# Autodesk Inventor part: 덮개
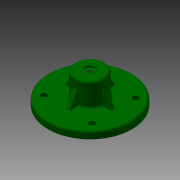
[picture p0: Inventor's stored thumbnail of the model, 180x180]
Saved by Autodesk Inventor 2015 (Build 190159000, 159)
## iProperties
Created: 2017-08
Part Number: 덮개
Material: 알루미늄 6061
Document SubType Name: Modeling
Designer: mduedu
Density: 2.71 g/cm^3
Mass: 358.12 g
Surface Area: 294.002 cm^2
Volume: 132.148 cm^3
Appearance: 알루미늄 - 평지
Author: mduedu
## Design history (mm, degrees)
sketch "스케치1"
  geometry: C1 r 57.5 at (0, 0); 1 further point
  constraints: 1 centre point, 1 coincident
  dimensions: "d69" = 115 diameter of C1
extrude "돌출1" new body sketch "스케치1" distance "d5" = 10; taper "d6" = 0 deg
sketch "스케치2"
  geometry: C1 r 20 at (0, 0); 1 further point
  constraints: 1 centre point, 1 coincident
  dimensions: "d55" = 40 diameter of C1
extrude "돌출2" join sketch "스케치2" distance "d9" = 32; taper "d10" = 0 deg
sketch "스케치3"
  geometry: L1 (-26, -26)-(26, -26); L2 (26, -26)-(26, 26); L3 (26, 26)-(-26, 26); L4 (-26, 26)-(-26, -26); L5 (-26, -26)-(26, 26); L6 (26, -26)-(-26, 26); 1 further point
  constraints: 12 end point, 2 midpoint, 2 parallel, 2 perpendicular, 1 horizontal
  dimensions: "d11" = 52 distance of L3.end L2.end
extrude "돌출3" join sketch "스케치3" distance "d12" = 6; taper "d13" = 0 deg
sketch "스케치4"
  geometry: L1 (-17, -17)-(17, -17); L2 (17, -17)-(17, 17); L3 (17, 17)-(-17, 17); L4 (-17, 17)-(-17, -17); L5 (-17, -17)-(17, 17); L6 (17, -17)-(-17, 17); 1 further point
  constraints: 12 end point, 2 midpoint, 2 parallel, 2 perpendicular, 1 horizontal
  dimensions: "d14" = 34 distance of L2.end L3.end
extrude "돌출4" cut sketch "스케치4" distance "d16" = 5; taper "d17" = 0 deg
sketch "스케치5"
  geometry: C1 r 9 at (0, 0); 1 further point
  constraints: 1 centre point, 1 coincident
  dimensions: "d18" = 18 diameter of C1
extrude "돌출5" cut sketch "스케치5" distance "d19" = 34; taper "d20" = 0 deg
sketch "스케치6"
  geometry: 2 further points
  constraints: 1 coincident
hole "구멍1" sketch "스케치6" at (0, 0) diameter "d21" = 5.917; stored, may be unused: countersink angle "d25" = 90 deg, drill point angle "d27" = 118 deg; dims "d22" = 6, "d23" = 14, "d24" = 2, "d26" = 8
fillet "모깎기3" dims "d38" = 3
fillet "모깎기4" dims "d39" = 3
fillet "모깎기5" dims "d40" = 3
chamfer "모따기2" distance "d70" = 6; stored, may be unused: second distance "d71" = 2, angle "d72" = 45 deg
chamfer "모따기1" distance "d41" = 1; stored, may be unused: second distance "d42" = 2, angle "d43" = 45 deg
fillet "모깎기6" dims "d44" = 3
fillet "모깎기7" dims "d45" = 3
fillet "모깎기8" dims "d46" = 3
sketch "스케치9"
  geometry: L1 (-33, -30)-(33, -30); L2 (33, -30)-(33, 30); L3 (33, 30)-(-33, 30); L4 (-33, 30)-(-33, -30); L5 (-33, -30)-(33, 30); L6 (33, -30)-(-33, 30); C1 r 54.5 at (0, 0) reference; 3 further points
  constraints: 12 end point, 2 coincident, 2 midpoint, 2 parallel, 2 point on line, 1 horizontal, 1 perpendicular
  dimensions: "d77" = 66 distance of L2.end L3.end; "d79" = 60 distance of L1.end L2.end
hole "구멍3" sketch "스케치9" at (-33, -30), (-33, 30), (33, 30), (33, -30) diameter "d48" = 4.5; stored, may be unused: countersink angle "d52" = 90 deg, drill point angle "d54" = 0 deg; dims "d49" = 6, "d50" = 8, "d51" = 4.6, "d53" = 8
sketch "스케치10"
  geometry: L1 (-7, 40)-(-2.958, 40) reference; L2 (-2.958, 40)-(-2.958, 33) reference; L3 (-2.958, 33)-(-6, 33) reference; L4 (-9, 30)-(-9, -1) reference; L5 (-9, -1)-(-14, -1) reference; L6 (-17, -4)-(-17, -6) reference; L7 (-17, -6)-(-25, -6) reference; L8 (-25, -6)-(-26, -5) reference; L9 (-26, -5)-(-26, 0) reference; L10 (-26, 0)-(-57.5, 0) reference; L11 (-54.5, 10)-(-23, 10) reference; L12 (-20, 13)-(-20, 39) reference; L13 (-17, 42)-(-7, 42) reference; L14 (-7, 42)-(-7, 40) reference; L15 (2.958, 40)-(7, 40) reference; L16 (7, 40)-(7, 42) reference; L17 (7, 42)-(17, 42) reference; L18 (20, 39)-(20, 13) reference; L19 (23, 10)-(54.5, 10) reference; L20 (57.5, 0)-(26, 0) reference; L21 (26, 0)-(26, -5) reference; L22 (26, -5)-(25, -6) reference; L23 (25, -6)-(17, -6) reference; L24 (17, -6)-(17, -4) reference; L25 (14, -1)-(9, -1) reference; L26 (9, -1)-(9, 30) reference; L27 (6, 33)-(2.958, 33) reference; L28 (2.958, 33)-(2.958, 40) reference; L29 (31.547, 10)-(20, 30); L30 (-57.5, 0)-(-57.5, 7) reference; L31 (57.5, 7)-(57.5, 0) reference; A1 r 3 centre (-6, 30) between (-6, 33) and (-9, 30) reference; A2 r 3 centre (-14, -4) between (-14, -1) and (-17, -4) reference; A3 r 3 centre (-23, 13) between (-23, 10) and (-20, 13) reference; A4 r 3 centre (-17, 39) between (-17, 42) and (-20, 39) reference; A5 r 3 centre (17, 39) between (20, 39) and (17, 42) reference; A6 r 3 centre (23, 13) between (20, 13) and (23, 10) reference; A7 r 3 centre (14, -4) between (17, -4) and (14, -1) reference; A8 r 3 centre (6, 30) between (9, 30) and (6, 33) reference; A9 r 3 centre (-54.5, 7) between (-54.5, 10) and (-57.5, 7) reference; 2 further points
  constraints: 2 end point, 2 point on line, 1 other
  dimensions: "d56" = 20 distance from line of L29.end L19; "d57" = 120 deg angle of L29 L19
feature "리브1" sketch "스케치10" dims "d58" = 1, "d59" = 6, "d60" = 0, "d61" = 0, "d62" = 1, "d63" = 1
fillet "모깎기9" dims "d64" = 1
fillet "모깎기10" dims "d65" = 1
node "솔리드1"
pattern_circular "원형 패턴1" dims "d67" = 360 deg
node "절단 모서리 투영1"
